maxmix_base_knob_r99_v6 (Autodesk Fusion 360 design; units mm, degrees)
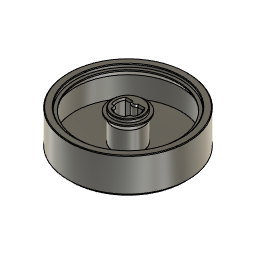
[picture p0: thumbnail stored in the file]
sketch "Sketch1" plane through (0, 0, 0) normal (0, 0, 1) x axis (1, 0, 0)
  line L1 (-2.5981, 1.5) -> (2.5981, 1.5)
  line L2 (0, -3) -> (0, 1.5)
  line L3 (-2.8723, 2) -> (2.8723, 2)
  circle C1 centre (0, 0) radius 19.7
  arc A1 centre (0, 0) radius 3 clockwise from (2.5981, 1.5) to (-2.5981, 1.5)
  arc A2 centre (0, 0) radius 3.5 clockwise from (2.8723, 2) to (-2.8723, 2)
  point P1 (0, 0)
  point P2 (0, 0)
  point P4 (0, 1.5)
  point P5 (0, -3)
  point P3 (0, 0)
  coincident P1 P2
  concentric C1 A1
  horizontal L1
  coincident L1 P4
  coincident P5 A1
  perpendicular L1 L2
  coincident P3 L2
  dimension "d1" diameter C1 = 39.4
  dimension "d8" diameter A1 = 6
  dimension "d9" distance P4 P5 = 4.5
  dimension "d10" = 0.5
extrude "Extrude1" new body sketch "Sketch1" profile of C1 along normal blind 12
extrude "Extrude2" cut sketch "Sketch1" profile of A2 L3 along normal blind 10
sketch "Sketch2" plane through (0, 0, 0) normal (0, 0, -1) x axis (1, 0, 0)
  line L1 (-2.8723, -2) -> (2.8723, -2)
  arc A1 centre (0, 0) radius 3.5 clockwise from (-2.8723, -2) to (2.8723, -2)
  circle C1 centre (0, 0) radius 19.7
  circle C2 centre (0, 0) radius 5
  circle C3 centre (0, 0) radius 17.5
  point P1 (0, 0)
  point P5 (0, 0)
  coincident P1 P5
  concentric A1 C3
  dimension "d11" diameter C2 = 10
  dimension "d12" diameter C3 = 35
extrude "Extrude3" cut sketch "Sketch2" profile of C2 C3 against normal blind 10
chamfer "Chamfer1" distance 1
chamfer "Chamfer3" distance 0.2
sketch "Sketch4" plane through (0, 0, 10) normal (0, 0, -1) x axis (1, 0, 0)
  line L1 (2.8723, -2) -> (-2.8723, -2)
  line L2 (-2.5981, -1.5) -> (2.5981, -1.5)
  line L3 (-2.8723, -2) -> (2.8723, -2)
  line L4 (-2.6812, 2.2498) -> (0, 0)
  line L5 (0, 3) -> (0, -1.5)
  line L6 (2.6812, 2.2498) -> (0, 0)
  line L7 (0, -2.9) -> (0, -1.5)
  line L8 (3.3706, 2.8283) -> (2.6812, 2.2498)
  line L9 (-3.3706, 2.8283) -> (-2.6812, 2.2498)
  arc A1 centre (0, 0) radius 3.5 clockwise from (-2.8723, -2) to (2.8723, -2)
  arc A2 centre (0, 0) radius 3 clockwise from (-2.5981, -1.5) to (2.5981, -1.5)
  arc A3 centre (0, 0) radius 3.5 clockwise from (-2.8723, -2) to (2.8723, -2)
  arc A4 centre (-3.3706, 2.8283) radius 1.5 clockwise from (-1.8759, 2.9548) to (-3.2357, 1.3343)
  arc A5 centre (0, -2.9) radius 1.5 clockwise from (-1.2, -2) to (1.2, -2)
  arc A6 centre (3.3706, 2.8283) radius 1.5 clockwise from (3.2357, 1.3343) to (1.8759, 2.9548)
  point P12 (0, 0)
  point P15 (0, 0)
  point P18 (0, 0)
  point P19 (-2.6812, 2.2498)
  point P20 (2.6812, 2.2498)
  point P16 (0, -1.5)
  point P21 (0, -1.5)
  point P22 (0, -2.9)
  point P23 (0, -2.9)
  point P25 (-3.3706, 2.8283)
  point P26 (-3.3706, 2.8283)
  point P24 (3.3706, 2.8283)
  point P27 (3.3706, 2.8283)
  point P28 (-1.8759, 2.9548)
  point P29 (-3.2357, 1.3343)
  point P30 (-1.2, -2)
  point P31 (1.2, -2)
  point P32 (3.2357, 1.3343)
  point P33 (1.8759, 2.9548)
  point P34 (0, -1.4)
  point P35 (-2.2215, 1.8641)
  point P36 (2.2215, 1.8641)
  point P37 (2.2981, 1.9284)
  point P38 (-2.2981, 1.9284)
  coincident P12 P15
  coincident P12 P18
  coincident A1 P19
  coincident A1 P20
  coincident P16 P21
  perpendicular L2 L7
  coincident P22 P23
  collinear L4 L9
  collinear L6 L8
  coincident P25 P26
  coincident P24 P27
  equal A4 A6
  equal A5 A6
  coincident A1 P28
  coincident A1 P29
  coincident L1 P30
  coincident L1 P31
  coincident A1 P32
  coincident A1 P33
  coincident A5 P34
  coincident A4 P35
  coincident A6 P36
  coincident L5 P34
  coincident L4 P35
  coincident L6 P36
  coincident A2 P37
  coincident A2 P38
  coincident L4 P38
  coincident L6 P37
  dimension "d26" angle L5 L6 = 50 (= "d27")
  dimension "d27" angle L4 L5 = 50
  dimension "d28" diameter A4 = 3
  dimension "d32" distance L2 P34 = 0.1
  dimension "d33" distance P36 P37 = 0.1 (= "d32")
  dimension "d34" distance P35 P38 = 0.1 (= "d32")
extrude "Extrude4" add sketch "Sketch4" profile of L1 A1 A3 L3 A5 A4 A6 to an object
chamfer "Chamfer4" distance 0.5
sketch "Sketch3" plane through (0, 0, 0) normal (0, 1, 0) x axis (1, 0, 0)
  line L1 (-17.5, -10) -> (-17.5, 0)
  line L2 (-5, 0) -> (-5, -10)
  line L3 (-5, -3.1321) -> (-6, -1.4)
  line L4 (-17.5, -3.1321) -> (-16.5, -1.4)
  line L5 (-5, -3.1321) -> (-17.5, -3.1321)
  line L6 (-16.5, -1.4) -> (-6, -1.4)
  line L7 (-6, -1) -> (-6, -1.4)
  line L8 (-5, -1) -> (-6, -1)
  line L9 (-16.5, -1) -> (-16.5, -1.4)
  line L10 (-17.5, -1) -> (-16.5, -1)
  point P2 (-17.5, 0)
  point P5 (-17.5, 0)
  point P3 (-17.5, -10)
  point P6 (-17.5, -10)
  point P4 (-5, -10)
  point P7 (-5, -10)
  point P10 (-5, -3.1321)
  point P12 (-17.5, -3.1321)
  point P14 (-5, -1)
  point P16 (-17.5, -1)
  point P8 (-5, 0)
  point P17 (-5, 0)
  point P15 (-16.5, -1)
  point P11 (-16.5, -1.4)
  coincident P2 P5
  coincident P3 P6
  coincident P4 P7
  coincident L2 P10
  coincident L1 P12
  perpendicular L2 L5
  horizontal L6
  perpendicular L6 L7
  coincident L2 P14
  perpendicular L2 L8
  perpendicular L6 L9
  coincident L1 P16
  perpendicular L1 L10
  collinear L8 L10
  equal L8 L10
  coincident P8 P17
  dimension "d16" angle L1 L4 = 30
  dimension "d19" distance P15 P16 = 1
  dimension "d20" distance P5 L10 = 1
  dimension "d21" distance P11 P15 = 0.4
revolve "Revolve1" sketch "Sketch3" AlongAngle 360
chamfer "Chamfer2" distance 0.2
move "Move1" RotateAngle 180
